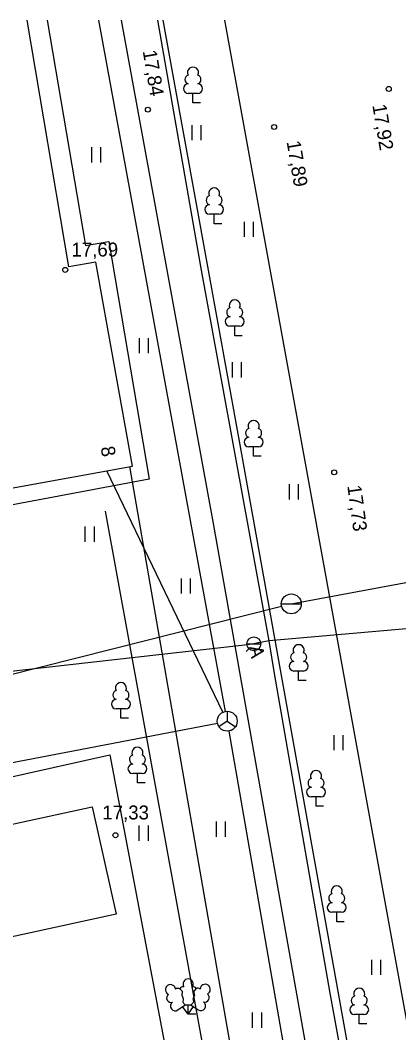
# Model space of a CAD drawing. Extents: x 713540 to 713867, y 6589774 to 6590061.
# Drawn here: x 713651.7 to 713670.7, y 6590009.8 to 6590060.6 of the extents above; entities that cross this region are included whole.
import ezdxf

# ---------------------------------------------------------------- set-up
doc = ezdxf.new("R2010")
doc.units = 0
for name, color, linetype in [('AED', 7, 'Continuous'), ('HALJASTUS', 7, 'Continuous'), ('HOONE', 7, 'Continuous'), ('KORGUS', 7, 'Continuous'), ('PUU', 7, 'Continuous'), ('SIKAEV', 7, 'Continuous'), ('SITRASS', 7, 'Continuous'), ('TEE', 7, 'Continuous'), ('VKAEV', 7, 'Continuous'), ('VTRASS', 7, 'Continuous')]:
    doc.layers.add(name, color=color, linetype=linetype)

msp = doc.modelspace()

# ---------------------------------------------------------------- linework, layer by layer
at = {"layer": 'AED'}
msp.add_lwpolyline([(713663.323, 6590003.114), (713657.209, 6590038.24)], dxfattribs=at)
at = {"layer": 'HALJASTUS'}
for p, q in [((713660.32, 6590055.373), (713660.32, 6590054.612)), ((713660.775, 6590055.373), (713660.775, 6590054.612)), ((713655.28, 6590054.259), (713655.28, 6590053.498)), ((713655.736, 6590054.259), (713655.736, 6590053.498)), ((713662.953, 6590050.523), (713662.953, 6590049.762)), ((713663.408, 6590050.523), (713663.408, 6590049.762)), ((713657.683, 6590044.686), (713657.683, 6590043.925)), ((713658.138, 6590044.686), (713658.138, 6590043.925)), ((713662.351, 6590043.476), (713662.351, 6590042.715)), ((713662.806, 6590043.476), (713662.806, 6590042.715)), ((713665.21, 6590037.348), (713665.21, 6590036.587)), ((713665.665, 6590037.348), (713665.665, 6590036.587)), ((713654.96, 6590035.227), (713654.96, 6590034.466)), ((713655.415, 6590035.227), (713655.415, 6590034.466)), ((713659.794, 6590032.629), (713659.794, 6590031.868)), ((713660.25, 6590032.629), (713660.25, 6590031.868)), ((713667.453, 6590024.765), (713667.453, 6590024.004)), ((713667.908, 6590024.765), (713667.908, 6590024.004)), ((713657.672, 6590020.224), (713657.672, 6590019.462)), ((713658.127, 6590020.224), (713658.127, 6590019.462)), ((713661.541, 6590020.424), (713661.541, 6590019.663)), ((713661.996, 6590020.424), (713661.996, 6590019.663)), ((713669.348, 6590013.494), (713669.348, 6590012.733)), ((713669.803, 6590013.494), (713669.803, 6590012.733)), ((713663.364, 6590010.841), (713663.364, 6590010.079)), ((713663.819, 6590010.841), (713663.819, 6590010.079))]:
    msp.add_line(p, q, dxfattribs=at)
msp.add_lwpolyline([(713655.98, 6590036), (713661.349, 6590006.549)], dxfattribs=at)
at = {"layer": 'HOONE'}
for points in [[(713639.902, 6590048.748), (713638.559, 6590048.521), (713640.803, 6590035.264), (713657.339, 6590038.264), (713655.499, 6590048.497), (713654.156, 6590048.27), (713652.063, 6590060.636)], [(713643.269, 6590018.555), (713655.327, 6590021.172), (713656.52, 6590015.784), (713644.523, 6590013.163), (713643.269, 6590018.555)]]:
    msp.add_lwpolyline(points, dxfattribs=at)
at = {"layer": 'KORGUS'}
for centre in [(713670.22, 6590057.19), (713658.12, 6590056.15), (713664.46, 6590055.28), (713653.97, 6590048.11), (713667.48, 6590037.95), (713656.49, 6590019.74)]:
    msp.add_circle(centre, 0.125, dxfattribs=at)
at = {"layer": 'PUU'}
for p, q in [((713660.624, 6590056.966), (713660.144, 6590056.966)), ((713660.384, 6590056.491), (713660.384, 6590056.966)), ((713660.764, 6590056.491), (713660.384, 6590056.491)), ((713661.689, 6590050.903), (713661.209, 6590050.903)), ((713661.449, 6590050.428), (713661.449, 6590050.903)), ((713661.829, 6590050.428), (713661.449, 6590050.428)), ((713662.722, 6590045.282), (713662.242, 6590045.282)), ((713662.482, 6590044.807), (713662.482, 6590045.282)), ((713662.862, 6590044.807), (713662.482, 6590044.807)), ((713663.67, 6590039.231), (713663.19, 6590039.231)), ((713663.43, 6590038.756), (713663.43, 6590039.231)), ((713663.81, 6590038.756), (713663.43, 6590038.756)), ((713665.932, 6590027.979), (713665.452, 6590027.979)), ((713665.692, 6590027.504), (713665.692, 6590027.979)), ((713666.072, 6590027.504), (713665.692, 6590027.504)), ((713657.005, 6590026.084), (713656.525, 6590026.084)), ((713656.765, 6590025.609), (713656.765, 6590026.084)), ((713657.145, 6590025.609), (713656.765, 6590025.609)), ((713657.836, 6590022.837), (713657.356, 6590022.837)), ((713657.596, 6590022.362), (713657.596, 6590022.837)), ((713657.976, 6590022.362), (713657.596, 6590022.362)), ((713666.807, 6590021.669), (713666.327, 6590021.669)), ((713666.567, 6590021.194), (713666.567, 6590021.669)), ((713666.947, 6590021.194), (713666.567, 6590021.194)), ((713667.846, 6590015.875), (713667.366, 6590015.875)), ((713667.606, 6590015.4), (713667.606, 6590015.875)), ((713667.986, 6590015.4), (713667.606, 6590015.4)), ((713659.63, 6590010.971), (713659.99, 6590011.226)), ((713660.14, 6590010.751), (713659.865, 6590011.136)), ((713659.99, 6590011.226), (713660.285, 6590011.226)), ((713660.14, 6590010.751), (713660.14, 6590011.226)), ((713660.14, 6590010.751), (713660.41, 6590011.141)), ((713660.285, 6590011.226), (713660.645, 6590010.981)), ((713660.52, 6590010.751), (713660.14, 6590010.751)), ((713668.975, 6590010.745), (713668.495, 6590010.745)), ((713668.735, 6590010.27), (713668.735, 6590010.745)), ((713669.115, 6590010.27), (713668.735, 6590010.27))]:
    msp.add_line(p, q, dxfattribs=at)
for points in [[(713659.727, 6590012.038), (713659.83, 6590011.936), (713659.845, 6590011.906), (713659.845, 6590011.851), (713659.83, 6590011.761), (713659.83, 6590011.716), (713659.85, 6590011.636), (713659.89, 6590011.546), (713659.9, 6590011.501), (713659.895, 6590011.456), (713659.88, 6590011.391), (713659.88, 6590011.361), (713659.9, 6590011.321), (713659.925, 6590011.291), (713659.99, 6590011.226)], [(713660.543, 6590012.052), (713660.45, 6590011.936), (713660.435, 6590011.906), (713660.435, 6590011.851), (713660.45, 6590011.761), (713660.455, 6590011.716), (713660.435, 6590011.636), (713660.395, 6590011.546), (713660.385, 6590011.501), (713660.39, 6590011.456), (713660.405, 6590011.391), (713660.405, 6590011.361), (713660.385, 6590011.321), (713660.36, 6590011.291), (713660.29, 6590011.226)]]:
    msp.add_lwpolyline(points, dxfattribs=at)
for centre, radius, start, end in [((713660.384, 6590058.011), 0.277, 332.5799, 207.4201), ((713660.214, 6590057.663), 0.233, 109.0217, 253.1415), ((713660.554, 6590057.663), 0.233, 286.8508, 70.9859), ((713660.146, 6590057.203), 0.238, 90.0016, 269.3953), ((713660.621, 6590057.203), 0.238, 270.6047, 89.9984), ((713661.449, 6590051.948), 0.277, 332.5799, 207.4201), ((713661.279, 6590051.601), 0.233, 109.0217, 253.1415), ((713661.619, 6590051.601), 0.233, 286.8508, 70.9859), ((713661.211, 6590051.141), 0.238, 90.0016, 269.3953), ((713661.686, 6590051.141), 0.238, 270.6047, 89.9984), ((713662.482, 6590046.327), 0.277, 332.5799, 207.4201), ((713662.312, 6590045.98), 0.233, 109.0217, 253.1415), ((713662.653, 6590045.98), 0.233, 286.8508, 70.9859), ((713662.245, 6590045.52), 0.238, 90.0016, 269.3953), ((713662.72, 6590045.52), 0.238, 270.6047, 89.9984), ((713663.43, 6590040.276), 0.277, 332.5799, 207.4201), ((713663.26, 6590039.929), 0.233, 109.0217, 253.1415), ((713663.6, 6590039.929), 0.233, 286.8508, 70.9859), ((713663.192, 6590039.469), 0.238, 90.0016, 269.3953), ((713663.667, 6590039.469), 0.238, 270.6047, 89.9984), ((713665.692, 6590029.024), 0.277, 332.5799, 207.4201), ((713665.522, 6590028.677), 0.233, 109.0217, 253.1415), ((713665.862, 6590028.677), 0.233, 286.8508, 70.9859), ((713665.454, 6590028.217), 0.238, 90.0016, 269.3953), ((713665.929, 6590028.217), 0.238, 270.6047, 89.9984), ((713656.765, 6590027.129), 0.277, 332.5799, 207.4201), ((713656.595, 6590026.782), 0.233, 109.0217, 253.1415), ((713656.936, 6590026.782), 0.233, 286.8508, 70.9859), ((713656.528, 6590026.322), 0.238, 90.0016, 269.3953), ((713657.003, 6590026.322), 0.238, 270.6047, 89.9984), ((713657.596, 6590023.882), 0.277, 332.5799, 207.4201), ((713657.426, 6590023.535), 0.233, 109.0217, 253.1415), ((713657.766, 6590023.535), 0.233, 286.8508, 70.9859), ((713657.358, 6590023.075), 0.238, 90.0016, 269.3953), ((713657.833, 6590023.075), 0.238, 270.6047, 89.9984), ((713666.567, 6590022.714), 0.277, 332.5799, 207.4201), ((713666.33, 6590021.906), 0.238, 90.0016, 269.3953), ((713666.397, 6590022.366), 0.233, 109.0217, 253.1415), ((713666.737, 6590022.366), 0.233, 286.8508, 70.9859), ((713666.805, 6590021.906), 0.238, 270.6047, 89.9984), ((713667.606, 6590016.92), 0.277, 332.5799, 207.4201), ((713667.436, 6590016.573), 0.233, 109.0217, 253.1415), ((713667.777, 6590016.573), 0.233, 286.8508, 70.9859), ((713667.369, 6590016.112), 0.238, 90.0016, 269.3953), ((713667.844, 6590016.112), 0.238, 270.6047, 89.9984), ((713660.14, 6590012.271), 0.256, 90.0013, 211.0159), ((713660.14, 6590012.271), 0.256, 328.9841, 89.9987), ((713659.256, 6590011.987), 0.256, 125.5389, 246.5536), ((713659.256, 6590011.987), 0.256, 4.5218, 125.5364), ((713659.643, 6590011.855), 0.202, 65.2382, 130.7412), ((713659.902, 6590011.938), 0.202, 84.7965, 150.2995), ((713660.377, 6590011.938), 0.202, 34.3857, 95.2035), ((713660.616, 6590011.864), 0.202, 50.3173, 111.1351), ((713661, 6590012.004), 0.256, 55.522, 176.5367), ((713661, 6590012.004), 0.256, 294.5049, 55.5195), ((713668.735, 6590011.79), 0.277, 332.5799, 207.4201), ((713659.284, 6590011.57), 0.224, 125.4667, 288.5349), ((713660.98, 6590011.586), 0.224, 252.5235, 55.5918), ((713668.565, 6590011.443), 0.233, 109.0217, 253.1415), ((713668.905, 6590011.443), 0.233, 286.8508, 70.9859), ((713659.494, 6590011.165), 0.237, 125.5377, 305.5366), ((713660.778, 6590011.177), 0.237, 235.5219, 55.5208), ((713668.497, 6590010.983), 0.238, 90.0016, 269.3953), ((713668.972, 6590010.983), 0.238, 270.6047, 89.9984)]:
    msp.add_arc(centre, radius, start, end, dxfattribs=at)
at = {"layer": 'SIKAEV'}
for p, q in [((713662.104, 6590025.961), (713662.104, 6590025.461)), ((713662.104, 6590025.461), (713661.689, 6590025.186)), ((713662.104, 6590025.461), (713662.519, 6590025.186))]:
    msp.add_line(p, q, dxfattribs=at)
msp.add_circle((713662.104, 6590025.461), 0.5, dxfattribs=at)
at = {"layer": 'SITRASS'}
for points in [[(713662.014, 6590025.952), (713655.659, 6590060.636)], [(713661.887, 6590025.911), (713656.055, 6590038.031)], [(713617.4, 6590014.56), (713618.53, 6590017.11), (713661.613, 6590025.367)], [(713662.189, 6590024.968), (713665.694, 6590004.762)]]:
    msp.add_lwpolyline(points, dxfattribs=at)
at = {"layer": 'TEE'}
for points in [[(713653.066, 6590060.636), (713654.979, 6590049.333), (713656.159, 6590049.533), (713658.178, 6590037.604), (713639.918, 6590034.172), (713638.17, 6590044.505), (713637.984, 6590044.473), (713637.235, 6590049.364)], [(713660.517, 6590000.069), (713667.464, 6590001.287), (713661.408, 6590035.387), (713656.791, 6590060.636)], [(713658.871, 6590060.636), (713662.701, 6590039.517), (713669.529, 6590001.451)], [(713672.229, 6590004.328), (713665.804, 6590039.691), (713661.981, 6590060.636)], [(713643.388, 6590020.908), (713656.207, 6590023.767), (713660.498, 6590001.178), (713658.504, 6590000.777), (713648.984, 6589998.66), (713647.543, 6589998.927), (713645.546, 6590001.73), (713644.549, 6590006.589), (713645.573, 6590007.272)]]:
    msp.add_lwpolyline(points, dxfattribs=at)
at = {"layer": 'VKAEV'}
for p, q in [((713664.822, 6590031.349), (713665.822, 6590031.349)), ((713663.088, 6590029.34), (713663.788, 6590029.34)), ((713663.191, 6590029.093), (713663.051, 6590028.953)), ((713663.685, 6590029.093), (713663.825, 6590028.953))]:
    msp.add_line(p, q, dxfattribs=at)
for centre, radius in [((713665.322, 6590031.349), 0.5), ((713663.438, 6590029.34), 0.35)]:
    msp.add_circle(centre, radius, dxfattribs=at)
at = {"layer": 'VTRASS'}
for points in [[(713684.308, 6589921.181), (713683.129, 6589927.373), (713681.203, 6589936.836), (713678.244, 6589950.963), (713676.229, 6589960.85), (713673.946, 6589973.712), (713673.362, 6589976.754), (713673.233, 6589977.362), (713672.25, 6589983.027), (713670.156, 6589996.06), (713667.268, 6590011.807), (713664.478, 6590027.857), (713664.208, 6590029.493), (713663.195, 6590035.091), (713660.78, 6590048.281), (713658.62, 6590060.636)], [(713665.322, 6590031.349), (713693.426, 6590036.568)], [(713639.008, 6590024.721), (713664.837, 6590031.227)], [(713680.062, 6590031.105), (713672.07, 6590030.177), (713664.208, 6590029.493)], [(713664.208, 6590029.493), (713663.589, 6590029.373), (713663.438, 6590029.34), (713663.119, 6590029.299), (713649.744, 6590027.784), (713635.847, 6590025.4)]]:
    msp.add_lwpolyline(points, dxfattribs=at)

# ---------------------------------------------------------------- texts
at = {"layer": 'HOONE'}
msp.add_text('8', height=0.7, rotation=280.5898, dxfattribs=at).set_placement((713655.74, 6590039.196))
at = {"layer": 'KORGUS'}
for s, rotation, p in [('17,84', 279.4795, (713657.857, 6590059.089)), ('17,92', 279.4795, (713669.392, 6590056.371)), ('17,89', 279.4795, (713665.085, 6590054.542)), ('17,73', 277.7119, (713668.133, 6590037.27))]:
    msp.add_text(s, height=0.7, rotation=rotation, dxfattribs=at).set_placement(p)
for s, p in [('17,69', (713654.282, 6590048.78)), ('17,33', (713655.831, 6590020.53))]:
    msp.add_text(s, height=0.7, dxfattribs=at).set_placement(p)
at = {"layer": 'TEE'}
msp.add_text('A', height=0.7, rotation=280.6252, dxfattribs=at).set_placement((713663.202, 6590029.19))

doc.saveas('drawing.dxf')
